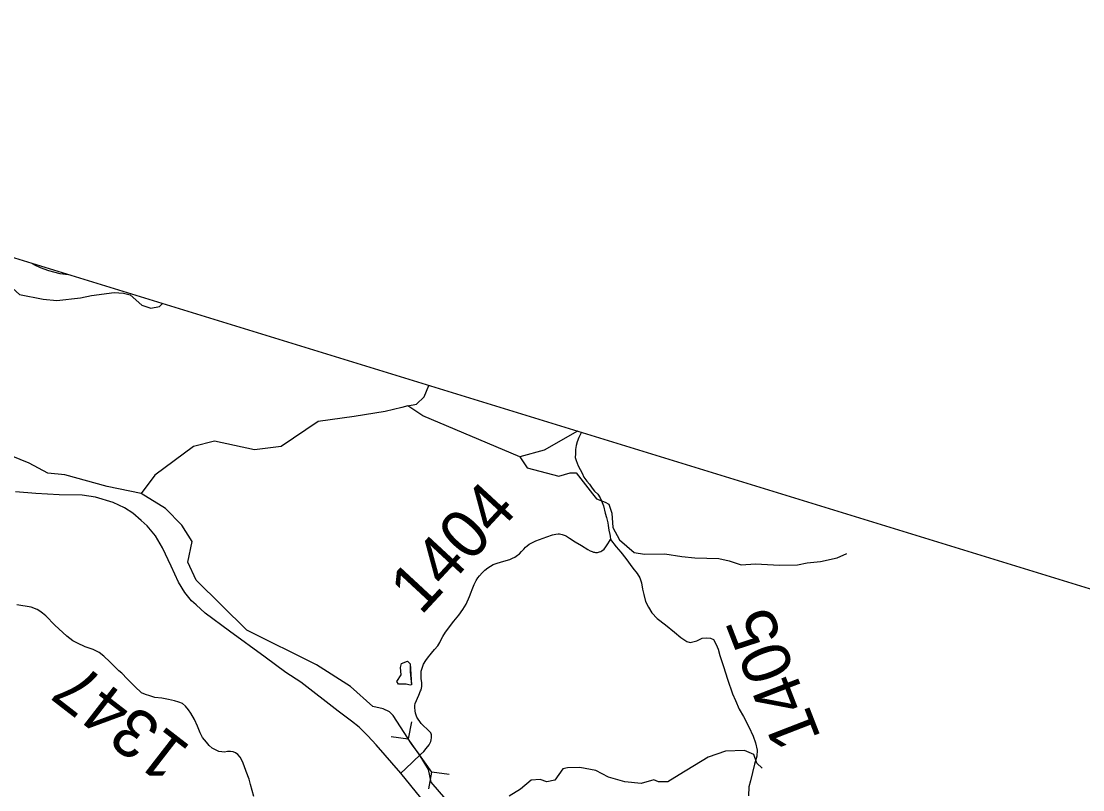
# Model space of a CAD drawing. Extents: x 1347947 to 1350662, y 1027710 to 1030532.
# Drawn here: x 1348247.6 to 1348346.4, y 1029049.4 to 1029120.9 of the extents above; entities that cross this region are included whole.
import ezdxf

# ---------------------------------------------------------------- set-up
doc = ezdxf.new("R2010")
doc.units = 0
for name, color, linetype in [('Default', 7, 'Continuous'), ('Prop Leader Line Light', 7, 'Continuous'), ('Prop WCC CELL', 7, 'Continuous')]:
    doc.layers.add(name, color=color, linetype=linetype)

msp = doc.modelspace()

# ---------------------------------------------------------------- linework, layer by layer
at = {"layer": 'Default'}
for p, q in [((1348283.923, 1029055.675), (1348283.617, 1029054.102)), ((1348282.03, 1029054.322), (1348283.617, 1029054.102)), ((1348285.837, 1029050.997), (1348283.617, 1029054.102)), ((1348285.531, 1029049.425), (1348285.837, 1029050.997)), ((1348287.424, 1029050.778), (1348285.837, 1029050.997))]:
    msp.add_line(p, q, dxfattribs=at)
for points in [[(1348242.712, 1029100.188), (1348244.044, 1029099.064), (1348244.254, 1029098.786), (1348245.143, 1029098.415), (1348246.074, 1029097.578), (1348246.769, 1029096.07), (1348247.437, 1029095.47), (1348249.627, 1029095.029), (1348250.916, 1029094.925), (1348253.105, 1029095.178), (1348254.137, 1029095.388), (1348256.235, 1029095.673), (1348257.129, 1029095.604), (1348257.748, 1029095.449), (1348258.835, 1029094.477), (1348259.652, 1029094.191), (1348260.465, 1029094.355), (1348260.758, 1029094.63)], [(1348248.623, 1029098.367), (1348248.837, 1029098.254), (1348249.348, 1029097.984), (1348250.144, 1029097.709), (1348251.188, 1029097.433), (1348252.007, 1029097.325)], [(1348258.772, 1029076.95), (1348255.581, 1029077.609), (1348251.646, 1029078.697), (1348250.058, 1029078.834), (1348248.327, 1029079.778), (1348235.216, 1029085.106), (1348232.961, 1029086.774), (1348231.101, 1029087.765), (1348229.196, 1029089.919), (1348228.182, 1029091.682), (1348227.738, 1029092.258), (1348226.964, 1029092.793), (1348226.255, 1029093.323), (1348225.257, 1029093.681)], [(1348283.595, 1029085.102), (1348284.409, 1029085.277), (1348285.096, 1029085.955), (1348285.547, 1029086.997)], [(1348283.595, 1029085.102), (1348283.041, 1029084.949), (1348281.471, 1029084.57), (1348278.605, 1029084.114), (1348275.242, 1029083.662), (1348271.802, 1029081.329), (1348269.315, 1029081.008), (1348265.585, 1029081.806), (1348263.636, 1029081.31), (1348260.023, 1029078.654), (1348258.772, 1029076.95)], [(1348299.386, 1029082.735), (1348296.274, 1029080.995), (1348294.009, 1029080.346), (1348284.981, 1029084.186), (1348283.595, 1029085.102)], [(1348299.742, 1029082.625), (1348299.73, 1029082.599), (1348299.51, 1029082.155), (1348299.365, 1029081.763), (1348299.273, 1029081.428), (1348299.2, 1029081.037), (1348299.188, 1029080.653), (1348299.154, 1029080.297), (1348299.255, 1029080.023), (1348299.342, 1029079.779), (1348299.448, 1029079.52), (1348299.637, 1029079.192), (1348299.822, 1029078.843), (1348299.986, 1029078.474), (1348300.261, 1029078.093), (1348300.489, 1029077.809), (1348300.763, 1029077.428), (1348300.955, 1029077.158), (1348301.266, 1029076.871), (1348301.481, 1029076.533), (1348301.605, 1029076.246), (1348301.792, 1029075.787), (1348301.957, 1029075.117), (1348302.08, 1029074.708), (1348302.195, 1029074.22), (1348302.246, 1029073.957), (1348302.287, 1029073.532), (1348302.392, 1029073.129), (1348302.428, 1029072.975), (1348302.466, 1029072.656)], [(1348294.009, 1029080.346), (1348294.695, 1029079.343), (1348297.658, 1029078.559), (1348298.704, 1029078.867), (1348299.257, 1029078.876), (1348300.774, 1029076.918), (1348301.163, 1029076.456), (1348301.967, 1029076.133), (1348302.312, 1029075.951), (1348302.585, 1029075.1), (1348302.676, 1029073.785), (1348303.292, 1029072.631), (1348304.667, 1029071.436), (1348305.632, 1029071.281), (1348307.527, 1029071.332), (1348309.093, 1029071.089), (1348310.314, 1029070.967), (1348312.529, 1029070.886), (1348313.501, 1029070.688), (1348314.626, 1029070.294), (1348315.95, 1029070.402), (1348318.188, 1029070.272), (1348319.85, 1029070.301), (1348320.772, 1029070.487), (1348321.997, 1029070.609), (1348323.549, 1029070.963), (1348324.461, 1029071.357)], [(1348282.93, 1029050.893), (1348280.63, 1029053.537), (1348279.861, 1029054.382), (1348279.062, 1029055.182), (1348278.338, 1029055.736), (1348277.114, 1029056.685), (1348273.614, 1029059.372), (1348272.214, 1029060.269), (1348270.301, 1029061.695), (1348266.988, 1029064.112), (1348264.704, 1029065.803), (1348263.869, 1029066.563), (1348263.438, 1029066.954), (1348262.813, 1029067.709), (1348262.247, 1029068.677), (1348261.562, 1029070.172), (1348260.751, 1029071.89), (1348260.089, 1029072.993), (1348259.327, 1029073.944), (1348258.769, 1029074.425), (1348257.984, 1029075.099), (1348257.21, 1029075.602), (1348256.164, 1029076.093), (1348254.504, 1029076.6), (1348253.266, 1029076.781), (1348251.115, 1029076.828), (1348248.956, 1029076.948), (1348247.071, 1029077.094)], [(1348284.651, 1029052.661), (1348283.934, 1029053.617), (1348282.214, 1029056.255), (1348281.869, 1029056.602), (1348281.302, 1029056.883), (1348280.339, 1029057.11), (1348278.251, 1029058.961), (1348275.073, 1029060.974), (1348268.583, 1029064.214), (1348263.88, 1029068.859), (1348263.116, 1029070.536), (1348263.52, 1029072.466), (1348262.552, 1029074.003), (1348261.02, 1029075.562), (1348258.772, 1029076.95)], [(1348284.781, 1029052.645), (1348285.071, 1029052.923), (1348285.307, 1029053.208), (1348285.58, 1029053.547), (1348285.742, 1029053.852), (1348285.771, 1029053.998), (1348285.799, 1029054.174), (1348285.793, 1029054.327), (1348285.792, 1029054.46), (1348285.714, 1029054.662), (1348285.604, 1029054.776), (1348284.823, 1029055.528), (1348284.429, 1029056.11), (1348284.305, 1029056.483), (1348284.264, 1029056.698), (1348284.242, 1029057.001), (1348284.231, 1029057.204), (1348284.277, 1029057.399), (1348284.598, 1029058.163), (1348284.772, 1029058.556), (1348284.823, 1029058.672), (1348284.871, 1029058.806), (1348284.896, 1029058.955), (1348284.893, 1029059.324), (1348284.831, 1029059.703), (1348284.824, 1029060.108), (1348284.842, 1029060.396), (1348284.878, 1029060.57), (1348284.976, 1029060.869), (1348285.055, 1029061.045), (1348285.277, 1029061.406), (1348285.506, 1029061.743), (1348285.654, 1029061.925), (1348285.793, 1029062.087), (1348286.085, 1029062.413), (1348286.371, 1029062.77), (1348286.559, 1029063.082), (1348286.689, 1029063.339), (1348286.837, 1029063.626), (1348287.089, 1029064.017), (1348287.873, 1029065.062), (1348288.335, 1029065.625), (1348288.714, 1029066.15), (1348289.018, 1029066.647), (1348289.335, 1029067.34), (1348289.49, 1029067.762), (1348289.573, 1029068.009), (1348289.761, 1029068.478), (1348289.934, 1029068.844), (1348290.102, 1029069.098), (1348290.245, 1029069.279), (1348290.515, 1029069.559), (1348290.767, 1029069.794), (1348291.045, 1029070.017), (1348291.287, 1029070.188), (1348291.534, 1029070.329), (1348291.909, 1029070.469), (1348292.53, 1029070.65), (1348293.081, 1029070.809), (1348293.325, 1029070.921), (1348293.545, 1029071.029), (1348293.797, 1029071.194), (1348293.978, 1029071.339), (1348294.168, 1029071.533), (1348294.384, 1029071.765), (1348294.552, 1029071.932), (1348294.686, 1029072.061), (1348294.879, 1029072.219), (1348295.181, 1029072.394), (1348295.509, 1029072.551), (1348296.172, 1029072.799), (1348296.533, 1029072.913), (1348297.048, 1029073.103), (1348297.36, 1029073.165), (1348297.577, 1029073.182), (1348297.713, 1029073.173), (1348297.955, 1029073.125), (1348298.23, 1029073.042), (1348298.355, 1029072.975), (1348298.627, 1029072.794), (1348299.18, 1029072.45), (1348299.77, 1029072.098), (1348300.331, 1029071.733), (1348300.555, 1029071.616), (1348300.734, 1029071.543), (1348300.886, 1029071.494), (1348300.981, 1029071.465), (1348301.071, 1029071.451), (1348301.159, 1029071.447), (1348301.247, 1029071.455), (1348301.353, 1029071.469), (1348301.443, 1029071.497), (1348301.55, 1029071.543), (1348301.64, 1029071.592), (1348301.861, 1029071.766), (1348302.011, 1029071.984), (1348302.206, 1029072.261), (1348302.366, 1029072.49), (1348302.466, 1029072.656)], [(1348302.466, 1029072.656), (1348302.982, 1029071.969), (1348303.407, 1029071.495), (1348303.885, 1029070.899), (1348304.537, 1029069.998), (1348304.923, 1029069.509), (1348305.173, 1029069.094), (1348305.353, 1029068.629), (1348305.429, 1029068.048), (1348305.558, 1029067.55), (1348305.724, 1029066.89)], [(1348305.724, 1029066.89), (1348305.98, 1029066.351), (1348306.291, 1029065.826), (1348306.801, 1029065.304), (1348307.578, 1029064.71), (1348308.411, 1029064.032), (1348308.994, 1029063.528), (1348309.558, 1029063.17), (1348309.88, 1029063.065), (1348310.485, 1029063.216), (1348310.99, 1029063.467), (1348311.384, 1029063.504), (1348311.764, 1029063.472), (1348312.034, 1029063.334), (1348312.297, 1029062.892), (1348312.467, 1029062.447), (1348312.641, 1029061.859), (1348312.97, 1029060.831), (1348313.345, 1029059.639), (1348313.803, 1029058.295), (1348314.096, 1029057.663), (1348314.427, 1029056.854), (1348314.824, 1029056.179), (1348315.332, 1029055.217), (1348315.724, 1029054.359), (1348315.965, 1029053.731), (1348316.116, 1029053.047), (1348316.074, 1029052.477), (1348315.863, 1029051.725), (1348315.498, 1029050.189), (1348315.344, 1029049.632), (1348315.292, 1029048.799)], [(1348255.853, 1029061.264), (1348255.288, 1029061.796), (1348254.85, 1029062.139), (1348254.293, 1029062.415), (1348253.548, 1029062.674), (1348252.827, 1029063.007), (1348252.41, 1029063.211), (1348251.85, 1029063.652), (1348250.726, 1029064.694), (1348249.885, 1029065.559), (1348249.583, 1029065.806), (1348249.318, 1029065.98), (1348249.065, 1029066.129), (1348248.53, 1029066.345), (1348247.2, 1029066.573)], [(1348269.259, 1029048.719), (1348268.952, 1029049.839), (1348268.809, 1029050.342), (1348268.524, 1029051.049), (1348268.338, 1029051.574), (1348268.186, 1029051.997), (1348267.98, 1029052.374), (1348267.746, 1029052.639), (1348267.535, 1029052.794), (1348267.316, 1029052.87), (1348267.085, 1029052.909), (1348266.8, 1029052.908), (1348266.519, 1029052.862), (1348266.257, 1029052.871), (1348265.991, 1029052.925), (1348265.676, 1029053.074), (1348265.38, 1029053.218), (1348265.078, 1029053.466), (1348264.838, 1029053.773), (1348264.486, 1029054.222), (1348264.26, 1029054.669), (1348263.996, 1029055.272), (1348263.724, 1029055.897), (1348263.397, 1029056.477), (1348263.177, 1029056.804), (1348262.889, 1029057.148), (1348262.604, 1029057.382), (1348262.259, 1029057.519), (1348261.869, 1029057.646), (1348261.312, 1029057.744), (1348260.7, 1029057.877), (1348260.021, 1029057.957), (1348259.583, 1029058.092), (1348259.17, 1029058.226), (1348258.792, 1029058.39), (1348258.18, 1029058.955), (1348257.446, 1029059.683), (1348256.966, 1029060.196), (1348256.677, 1029060.423), (1348255.853, 1029061.264)], [(1348283.427, 1029059.173), (1348282.714, 1029059.176), (1348282.56, 1029059.434), (1348282.978, 1029060.043), (1348282.915, 1029060.737), (1348282.987, 1029061.119), (1348283.568, 1029061.325), (1348283.79, 1029061.083), (1348283.792, 1029060.329), (1348283.925, 1029059.14), (1348283.803, 1029059.08), (1348283.427, 1029059.173)], [(1348283.427, 1029059.173), (1348282.714, 1029059.176), (1348282.56, 1029059.434), (1348282.978, 1029060.043), (1348282.915, 1029060.737), (1348282.987, 1029061.119), (1348283.568, 1029061.325), (1348283.79, 1029061.083), (1348283.925, 1029059.14), (1348283.803, 1029059.08), (1348283.427, 1029059.173)], [(1348282.93, 1029050.893), (1348283.366, 1029051.316), (1348284.781, 1029052.645)], [(1348287.701, 1029047.804), (1348285.752, 1029050.071), (1348285.507, 1029051.243), (1348284.651, 1029052.661)], [(1348316.583, 1029051.357), (1348316.09, 1029051.815), (1348315.804, 1029052.629), (1348314.915, 1029053), (1348313.161, 1029052.942), (1348311.539, 1029052.389), (1348308.861, 1029050.737), (1348307.78, 1029050.095), (1348306.939, 1029050.082), (1348306.497, 1029050.278), (1348305.318, 1029049.938), (1348303.78, 1029050.088), (1348302.259, 1029050.519), (1348301.094, 1029051.15), (1348299.594, 1029051.411), (1348298.467, 1029051.398), (1348298.027, 1029051.307), (1348297.269, 1029050.247), (1348296.542, 1029050.094), (1348295.907, 1029050.316), (1348295.065, 1029050.243), (1348294.061, 1029049.412), (1348293.016, 1029048.757)], [(1348287.596, 1029045.249), (1348285.737, 1029047.442), (1348282.93, 1029050.893)]]:
    msp.add_lwpolyline(points, dxfattribs=at)
at = {"layer": 'Prop WCC CELL'}
msp.add_line((1348393.408, 1029053.781), (1348175.36, 1029120.929), dxfattribs=at)

# ---------------------------------------------------------------- texts
at = {"layer": 'Prop Leader Line Light'}
for s, rotation, p in [('1404', 47.16294, (1348284.81, 1029065.512)), ('1405', 111.20126, (1348322.081, 1029054.175)), ('1347', 142.26058, (1348263.515, 1029053.281))]:
    msp.add_text(s, height=4.5, rotation=rotation, dxfattribs=at).set_placement(p)

doc.saveas('drawing.dxf')
